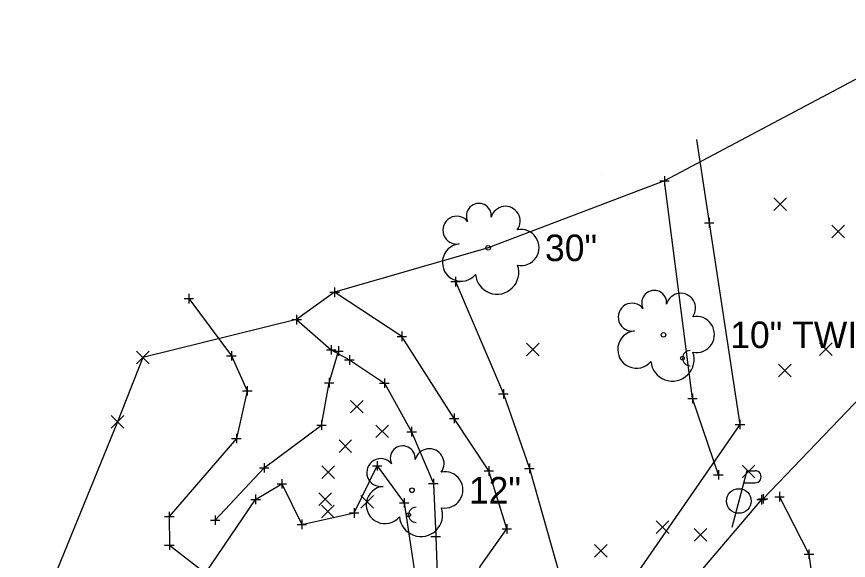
# Model space of a CAD drawing. Extents: x -4 to 139204, y -4 to 477121.
# Drawn here: x 139035.5 to 139123.3, y 477063 to 477120.4 of the extents above; entities that cross this region are included whole.
import ezdxf

# ---------------------------------------------------------------- set-up
doc = ezdxf.new("R2010")
doc.units = 0
for name, color, linetype in [('_CIVIL_CONSTRUCTION', 7, 'Continuous'), ('Default', 7, 'Continuous'), ('DR_X_Ditch', 7, 'Continuous'), ('GE_X_Alignment', 7, 'Continuous'), ('GE_X_Alignment_100_Bearings', 7, 'Continuous'), ('GE_X_Alignment_100_Cardinal_Points', 7, 'Continuous'), ('GE_X_Alignment_100_Curve_Data', 7, 'Continuous'), ('PV_X_Driveway', 7, 'Continuous'), ('RD_X_Fence', 7, 'Continuous'), ('RD_X_Gate', 7, 'Continuous'), ('SC_Scratch1', 7, 'Continuous'), ('SC_Scratch2', 7, 'Continuous'), ('SC_Scratch3', 7, 'Continuous'), ('SV_X_Terrain_Boundary', 7, 'Continuous'), ('VG_X_Text', 7, 'Continuous')]:
    doc.layers.add(name, color=color, linetype=linetype)

msp = doc.modelspace()

# ---------------------------------------------------------------- linework, layer by layer
at = {"layer": '_CIVIL_CONSTRUCTION'}
for p, q in [((139112.588, 477072.478), (139110.981, 477066.478)), ((139112.588, 477072.478), (139113.438, 477072.478)), ((139112.246, 477071.203), (139113.438, 477071.203))]:
    msp.add_line(p, q, dxfattribs=at)
msp.add_circle((139111.731, 477069.278), 1.3, dxfattribs=at)
msp.add_arc((139113.45, 477071.84), 0.638, 268.8767, 91.1233, dxfattribs=at)
at = {"layer": 'Default'}
msp.add_line((139097.371, 477103.724), (139097.371, 477103.724), dxfattribs=at)
at = {"layer": 'DR_X_Ditch'}
for points in [[(139082.68, 477039.621), (139082.879, 477045.088), (139081.854, 477051.65), (139083.67, 477057.87), (139084.434, 477062.351), (139087.249, 477066.327), (139085.344, 477072.452), (139081.689, 477077.998), (139076.163, 477086.656), (139069.076, 477091.309)], [(139065.071, 477088.425), (139068.722, 477085.24), (139070.63, 477084.165), (139074.327, 477081.721), (139077.204, 477076.592), (139079.496, 477071.125), (139079.747, 477065.535), (139080.041, 477057.632), (139078.626, 477051.044), (139075.806, 477039.501), (139076.261, 477034.97)]]:
    msp.add_lwpolyline(points, dxfattribs=at)
at = {"layer": 'GE_X_Alignment'}
for p, q in [((139115.414, 477099.948), (139116.748, 477101.282)), ((139115.414, 477101.282), (139116.748, 477099.948)), ((139121.539, 477097.062), (139122.873, 477098.397)), ((139121.539, 477098.397), (139122.873, 477097.062)), ((139089.31, 477084.619), (139090.644, 477085.954)), ((139089.31, 477085.954), (139090.644, 477084.619)), ((139120.233, 477084.651), (139121.567, 477085.986)), ((139120.233, 477085.986), (139121.567, 477084.651)), ((139048.175, 477083.774), (139049.509, 477085.109)), ((139048.175, 477085.109), (139049.509, 477083.774)), ((139115.919, 477082.386), (139117.253, 477083.721)), ((139115.919, 477083.721), (139117.253, 477082.386)), ((139070.747, 477078.569), (139072.081, 477079.905)), ((139070.747, 477079.905), (139072.081, 477078.569)), ((139045.488, 477076.971), (139046.822, 477078.307)), ((139045.488, 477078.307), (139046.822, 477076.971)), ((139073.428, 477075.965), (139074.762, 477077.301)), ((139073.428, 477077.301), (139074.762, 477075.965)), ((139069.539, 477074.385), (139070.873, 477075.72)), ((139069.539, 477075.72), (139070.873, 477074.385)), ((139067.735, 477071.657), (139069.069, 477072.992)), ((139067.735, 477072.992), (139069.069, 477071.657)), ((139112.077, 477071.731), (139113.411, 477073.066)), ((139112.077, 477073.066), (139113.411, 477071.731)), ((139067.413, 477068.798), (139068.747, 477070.133)), ((139067.413, 477070.133), (139068.747, 477068.798)), ((139071.842, 477068.524), (139073.176, 477069.858)), ((139071.842, 477069.858), (139073.176, 477068.524)), ((139067.694, 477067.502), (139069.028, 477068.836)), ((139067.694, 477068.836), (139069.028, 477067.502)), ((139103.001, 477065.837), (139104.335, 477067.172)), ((139103.001, 477067.172), (139104.335, 477065.837)), ((139107.024, 477065.039), (139108.358, 477066.374)), ((139107.024, 477066.374), (139108.358, 477065.039)), ((139096.487, 477063.348), (139097.821, 477064.683)), ((139096.487, 477064.683), (139097.821, 477063.348))]:
    msp.add_line(p, q, dxfattribs=at)
at = {"layer": 'GE_X_Alignment_100_Bearings'}
for p, q in [((139103.883, 477103.572), (139103.883, 477102.572)), ((139103.383, 477103.072), (139104.383, 477103.072)), ((139103.883, 477103.072), (139103.883, 477103.072)), ((139108.601, 477099.158), (139108.601, 477098.158)), ((139108.101, 477098.658), (139109.101, 477098.658)), ((139108.601, 477098.658), (139108.601, 477098.658)), ((139081.831, 477092.934), (139081.831, 477091.934)), ((139081.331, 477092.434), (139082.331, 477092.434)), ((139081.831, 477092.434), (139081.831, 477092.434)), ((139053.686, 477091.137), (139053.686, 477090.137)), ((139068.576, 477091.309), (139069.576, 477091.309)), ((139069.076, 477091.809), (139069.076, 477090.809)), ((139069.076, 477091.309), (139069.076, 477091.309)), ((139053.186, 477090.637), (139054.186, 477090.637)), ((139053.686, 477090.637), (139053.686, 477090.637)), ((139064.571, 477088.425), (139065.571, 477088.425)), ((139065.071, 477088.925), (139065.071, 477087.925)), ((139065.071, 477088.425), (139065.071, 477088.425)), ((139076.163, 477087.156), (139076.163, 477086.156)), ((139075.663, 477086.656), (139076.663, 477086.656)), ((139076.163, 477086.656), (139076.163, 477086.656)), ((139058.184, 477085.096), (139058.184, 477084.096)), ((139068.222, 477085.24), (139069.222, 477085.24)), ((139068.722, 477085.74), (139068.722, 477084.74)), ((139068.722, 477085.24), (139068.722, 477085.24)), ((139068.994, 477085.109), (139069.994, 477085.109)), ((139069.494, 477085.609), (139069.494, 477084.609)), ((139069.494, 477085.109), (139069.494, 477085.109)), ((139057.684, 477084.596), (139058.684, 477084.596)), ((139058.184, 477084.596), (139058.184, 477084.596)), ((139070.13, 477084.165), (139071.13, 477084.165)), ((139070.63, 477084.665), (139070.63, 477083.665)), ((139070.63, 477084.165), (139070.63, 477084.165)), ((139059.86, 477081.401), (139059.86, 477080.401)), ((139068.008, 477081.768), (139069.008, 477081.768)), ((139068.508, 477082.268), (139068.508, 477081.268)), ((139068.508, 477081.768), (139068.508, 477081.768)), ((139073.827, 477081.721), (139074.827, 477081.721)), ((139074.327, 477082.221), (139074.327, 477081.221)), ((139074.327, 477081.721), (139074.327, 477081.721)), ((139059.36, 477080.901), (139060.36, 477080.901)), ((139059.86, 477080.901), (139059.86, 477080.901)), ((139086.385, 477080.599), (139087.385, 477080.599)), ((139086.885, 477081.099), (139086.885, 477080.099)), ((139086.885, 477080.599), (139086.885, 477080.599)), ((139106.84, 477080.589), (139106.84, 477079.589)), ((139106.34, 477080.089), (139107.34, 477080.089)), ((139106.84, 477080.089), (139106.84, 477080.089)), ((139081.189, 477077.998), (139082.189, 477077.998)), ((139081.689, 477078.498), (139081.689, 477077.498)), ((139081.689, 477077.998), (139081.689, 477077.998)), ((139067.188, 477077.283), (139068.188, 477077.283)), ((139067.688, 477077.783), (139067.688, 477076.783)), ((139067.688, 477077.283), (139067.688, 477077.283)), ((139077.204, 477077.092), (139077.204, 477076.092)), ((139111.354, 477077.364), (139112.354, 477077.364)), ((139111.854, 477077.864), (139111.854, 477076.864)), ((139111.854, 477077.364), (139111.854, 477077.364)), ((139058.705, 477076.381), (139058.705, 477075.381)), ((139076.704, 477076.592), (139077.704, 477076.592)), ((139077.204, 477076.592), (139077.204, 477076.592)), ((139058.205, 477075.881), (139059.205, 477075.881)), ((139058.705, 477075.881), (139058.705, 477075.881)), ((139061.139, 477072.78), (139062.139, 477072.78)), ((139061.639, 477073.28), (139061.639, 477072.28)), ((139061.639, 477072.78), (139061.639, 477072.78)), ((139073.073, 477072.991), (139074.073, 477072.991)), ((139073.573, 477073.491), (139073.573, 477072.491)), ((139073.573, 477072.991), (139073.573, 477072.991)), ((139085.344, 477072.952), (139085.344, 477071.952)), ((139089.13, 477072.727), (139090.13, 477072.727)), ((139089.63, 477073.227), (139089.63, 477072.227)), ((139089.63, 477072.727), (139089.63, 477072.727)), ((139084.844, 477072.452), (139085.844, 477072.452)), ((139085.344, 477072.452), (139085.344, 477072.452)), ((139109.071, 477072.05), (139110.071, 477072.05)), ((139109.571, 477072.55), (139109.571, 477071.55)), ((139109.571, 477072.05), (139109.571, 477072.05)), ((139062.998, 477071.098), (139063.998, 477071.098)), ((139063.498, 477071.598), (139063.498, 477070.598)), ((139063.498, 477071.098), (139063.498, 477071.098)), ((139078.996, 477071.125), (139079.996, 477071.125)), ((139079.496, 477071.625), (139079.496, 477070.625)), ((139079.496, 477071.125), (139079.496, 477071.125)), ((139114.307, 477070.01), (139114.307, 477069.01)), ((139116.013, 477070.231), (139116.013, 477069.231)), ((139060.238, 477069.452), (139061.238, 477069.452)), ((139060.738, 477069.952), (139060.738, 477068.952)), ((139060.738, 477069.452), (139060.738, 477069.452)), ((139076.409, 477069.59), (139076.409, 477068.59)), ((139113.624, 477069.425), (139114.624, 477069.425)), ((139113.807, 477069.51), (139114.807, 477069.51)), ((139114.124, 477069.925), (139114.124, 477068.925)), ((139114.124, 477069.425), (139114.124, 477069.425)), ((139114.307, 477069.51), (139114.307, 477069.51)), ((139115.513, 477069.731), (139116.513, 477069.731)), ((139116.013, 477069.731), (139116.013, 477069.731)), ((139071.131, 477068.517), (139071.131, 477067.517)), ((139075.909, 477069.09), (139076.909, 477069.09)), ((139076.409, 477069.09), (139076.409, 477069.09)), ((139051.133, 477067.64), (139052.133, 477067.64)), ((139051.633, 477068.14), (139051.633, 477067.14)), ((139051.633, 477067.64), (139051.633, 477067.64)), ((139056.481, 477067.76), (139056.481, 477066.76)), ((139070.631, 477068.017), (139071.631, 477068.017)), ((139071.131, 477068.017), (139071.131, 477068.017)), ((139055.981, 477067.26), (139056.981, 477067.26)), ((139056.481, 477067.26), (139056.481, 477067.26)), ((139065.109, 477066.813), (139066.109, 477066.813)), ((139065.609, 477067.313), (139065.609, 477066.313)), ((139065.609, 477066.813), (139065.609, 477066.813)), ((139087.249, 477066.827), (139087.249, 477065.827)), ((139079.747, 477066.035), (139079.747, 477065.035)), ((139086.749, 477066.327), (139087.749, 477066.327)), ((139087.249, 477066.327), (139087.249, 477066.327)), ((139051.641, 477065.127), (139051.641, 477064.127)), ((139079.247, 477065.535), (139080.247, 477065.535)), ((139079.747, 477065.535), (139079.747, 477065.535)), ((139051.141, 477064.627), (139052.141, 477064.627)), ((139051.641, 477064.627), (139051.641, 477064.627)), ((139119.133, 477064.173), (139119.133, 477063.173)), ((139118.633, 477063.673), (139119.633, 477063.673)), ((139119.133, 477063.673), (139119.133, 477063.673))]:
    msp.add_line(p, q, dxfattribs=at)
at = {"layer": 'GE_X_Alignment_100_Cardinal_Points'}
for centre in [(139105.788, 477084.354), (139076.889, 477067.817)]:
    msp.add_circle(centre, 0.2, dxfattribs=at)
for centre in [(139106.588, 477084.354), (139077.689, 477067.817)]:
    msp.add_arc(centre, 0.8, 90, 270, dxfattribs=at)
at = {"layer": 'GE_X_Alignment_100_Curve_Data'}
for centre in [(139085.277, 477096.002), (139103.781, 477086.823), (139077.248, 477070.413)]:
    msp.add_circle(centre, 0.24, dxfattribs=at)
for centre, radius, start, end in [((139084.293, 477099.37), 1.317, 354.0047, 205.97412), ((139087.103, 477098.831), 1.553, 323.82996, 165.0376), ((139081.968, 477097.866), 1.471, 39.06254, 279.54124), ((139088.737, 477096.038), 1.915, 259.14531, 101.45961), ((139082.424, 477094.453), 1.974, 96.17219, 320.57371), ((139086.223, 477093.397), 2.284, 184.94757, 19.45715), ((139102.797, 477090.191), 1.317, 354.0047, 205.97412), ((139105.607, 477089.652), 1.553, 323.82996, 165.0376), ((139100.472, 477088.687), 1.471, 39.06254, 279.54124), ((139107.241, 477086.859), 1.915, 259.14531, 101.45961), ((139100.928, 477085.274), 1.974, 96.17219, 320.57371), ((139104.727, 477084.218), 2.284, 184.94757, 19.45715), ((139076.264, 477073.781), 1.317, 354.0047, 205.97412), ((139079.074, 477073.242), 1.553, 323.82996, 165.0376), ((139073.939, 477072.277), 1.471, 39.06254, 279.54124), ((139080.708, 477070.449), 1.915, 259.14531, 101.45961), ((139074.395, 477068.864), 1.974, 96.17219, 320.57371), ((139078.194, 477067.808), 2.284, 184.94757, 19.45715)]:
    msp.add_arc(centre, radius, start, end, dxfattribs=at)
at = {"layer": 'PV_X_Driveway'}
msp.add_lwpolyline([(139116.013, 477069.731), (139119.133, 477063.673), (139120.309, 477054.876)], dxfattribs=at)
at = {"layer": 'RD_X_Fence'}
msp.add_lwpolyline([(139114.124, 477069.425), (139097.626, 477050.067), (139068.264, 477026.835), (139055.528, 477014.997), (139027.688, 476991.135), (139019.001, 476984.321), (139015.388, 476979.86)], dxfattribs=at)
at = {"layer": 'RD_X_Gate'}
msp.add_line((139114.307, 477069.51), (139124.709, 477080.375), dxfattribs=at)
at = {"layer": 'SC_Scratch1'}
for points in [[(139109.571, 477072.05), (139106.84, 477080.089), (139103.883, 477103.072)], [(139081.831, 477092.434), (139086.885, 477080.599), (139089.63, 477072.727), (139094.342, 477056.019), (139093.051, 477051.088)], [(139056.481, 477067.26), (139061.639, 477072.78), (139067.688, 477077.283), (139068.508, 477081.768), (139069.494, 477085.109)]]:
    msp.add_lwpolyline(points, dxfattribs=at)
at = {"layer": 'SC_Scratch2'}
msp.add_lwpolyline([(139107.262, 477107.424), (139111.854, 477077.364), (139094.96, 477052.937), (139074.58, 477031.998), (139045.975, 477025.97)], dxfattribs=at)
at = {"layer": 'SC_Scratch3'}
msp.add_lwpolyline([(139053.686, 477090.637), (139058.184, 477084.596), (139059.86, 477080.901), (139058.705, 477075.881), (139051.633, 477067.64), (139051.641, 477064.627), (139055.462, 477061.652), (139060.738, 477069.452), (139063.498, 477071.098), (139065.609, 477066.813), (139071.131, 477068.017), (139073.573, 477072.991), (139076.409, 477069.09), (139078.09, 477057.888), (139073.469, 477045.379), (139071.206, 477039.094), (139066.85, 477033.126), (139068.313, 477027.937)], dxfattribs=at)
at = {"layer": 'SV_X_Terrain_Boundary'}
msp.add_lwpolyline([(139032.097, 476888.075), (139056.893, 476904.696), (139090.539, 476931.416), (139155.934, 476978.22), (139169.878, 477009.654), (139198.429, 477030.905), (139194.866, 477055.697), (139145.075, 477113.146), (139136.557, 477120.408), (139103.883, 477103.072), (139085.277, 477096.002), (139069.076, 477091.309), (139065.071, 477088.425), (139048.842, 477084.442), (139046.155, 477077.639), (139022.377, 477019.422)], dxfattribs=at)

# ---------------------------------------------------------------- texts
at = {"layer": 'VG_X_Text'}
for s, p in [('30"', (139091.277, 477094.602)), (' 10" TWIN', (139109.781, 477085.423)), ('12"', (139083.248, 477069.013))]:
    msp.add_text(s, height=2.8, dxfattribs=at).set_placement(p)

doc.saveas('drawing.dxf')
